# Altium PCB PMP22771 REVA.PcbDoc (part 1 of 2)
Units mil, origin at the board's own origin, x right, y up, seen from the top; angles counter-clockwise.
Board outline 3622.05 x 2204.72 mil, 4 copper layers (Top Layer, Signal Layer 1, Signal Layer 2, Bottom Layer), stack 35.634 mil thick; 91 components, 43 nets, 205 pads, 79 vias.
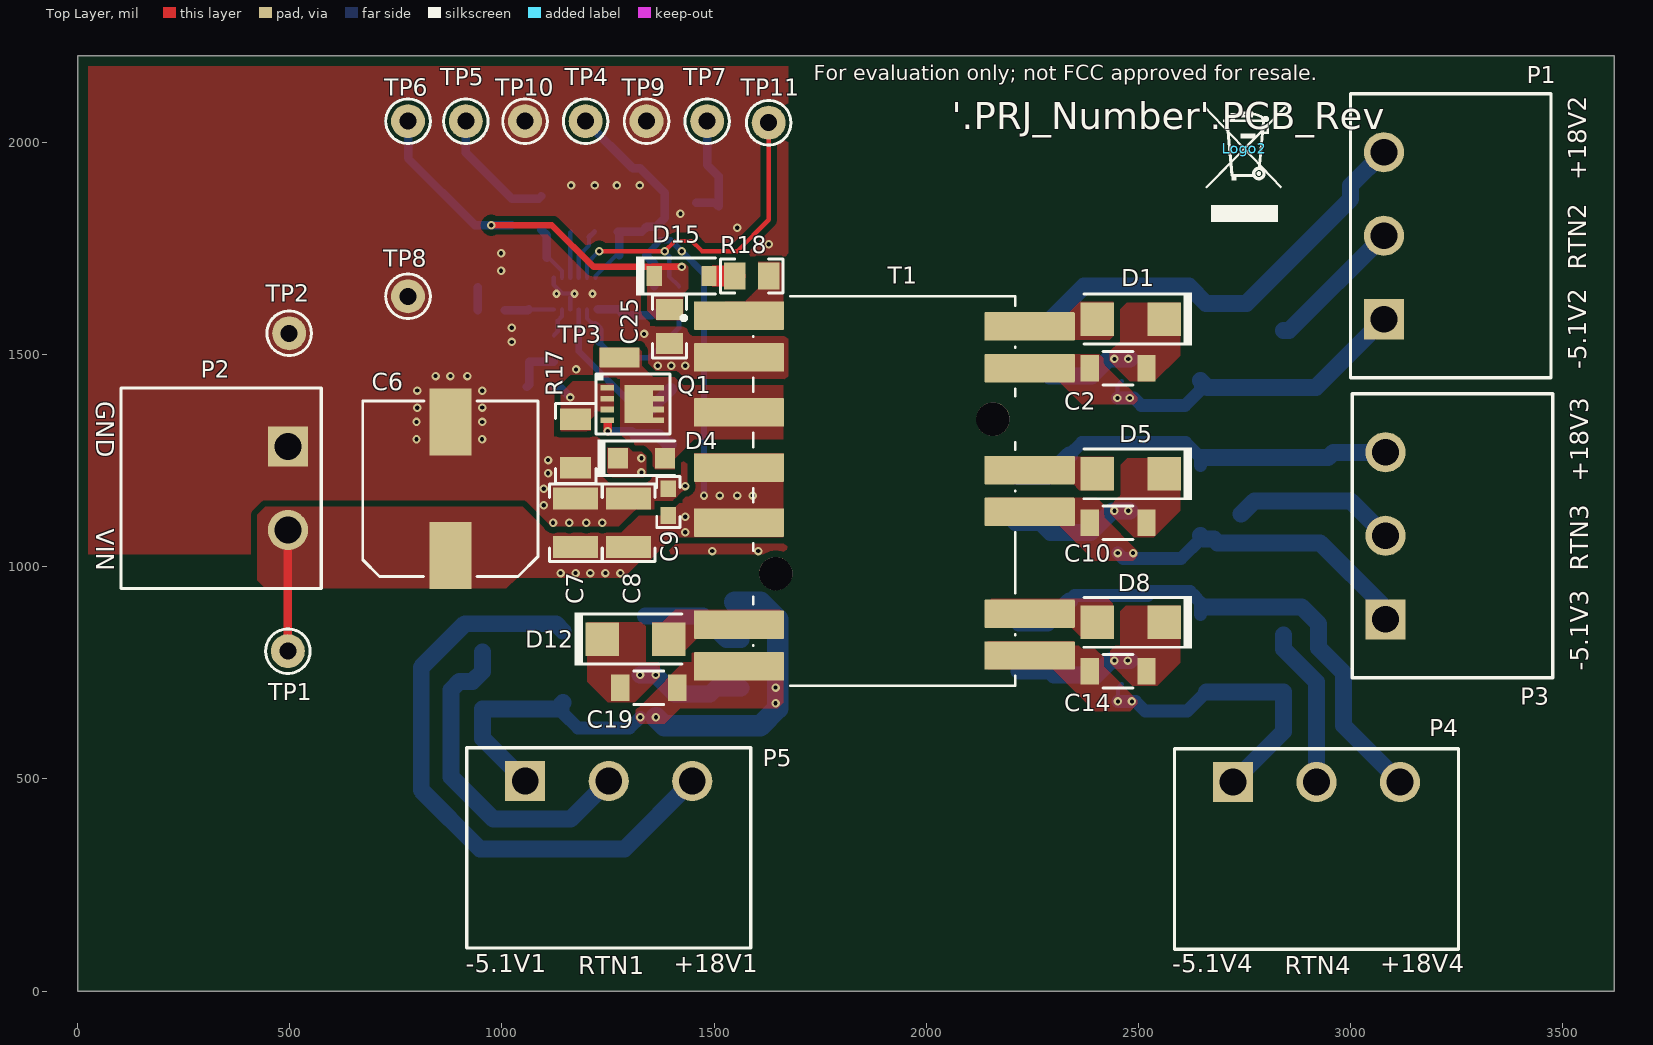
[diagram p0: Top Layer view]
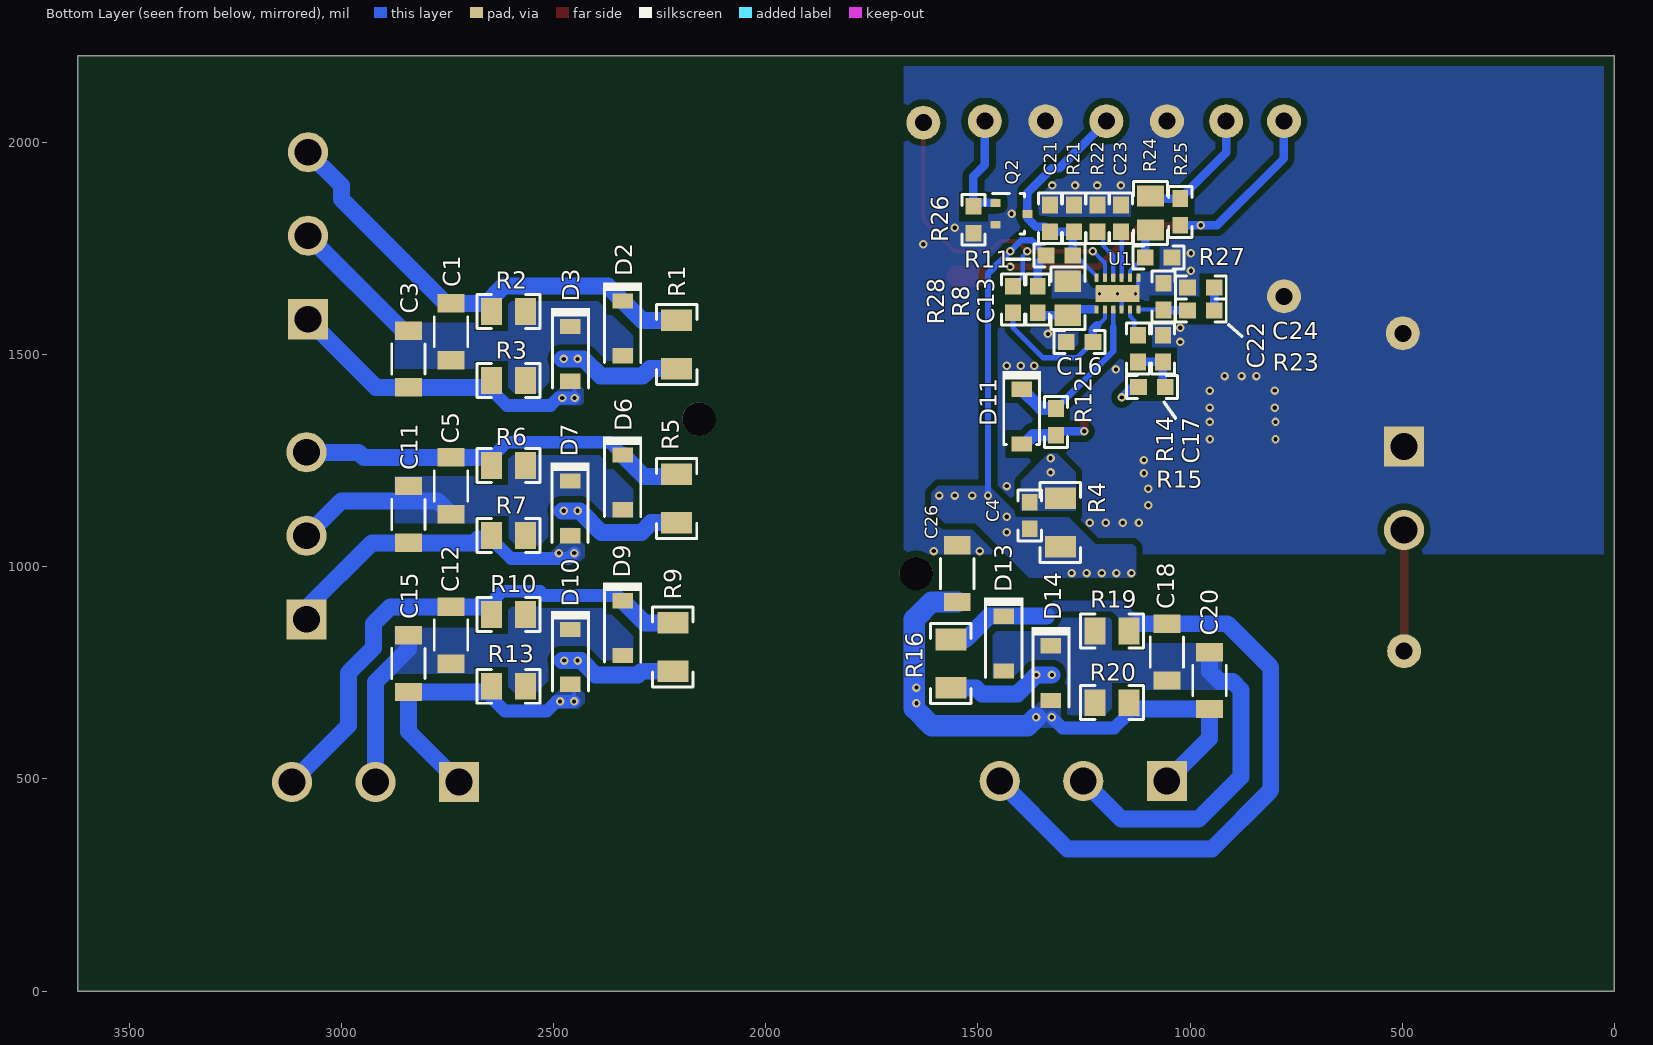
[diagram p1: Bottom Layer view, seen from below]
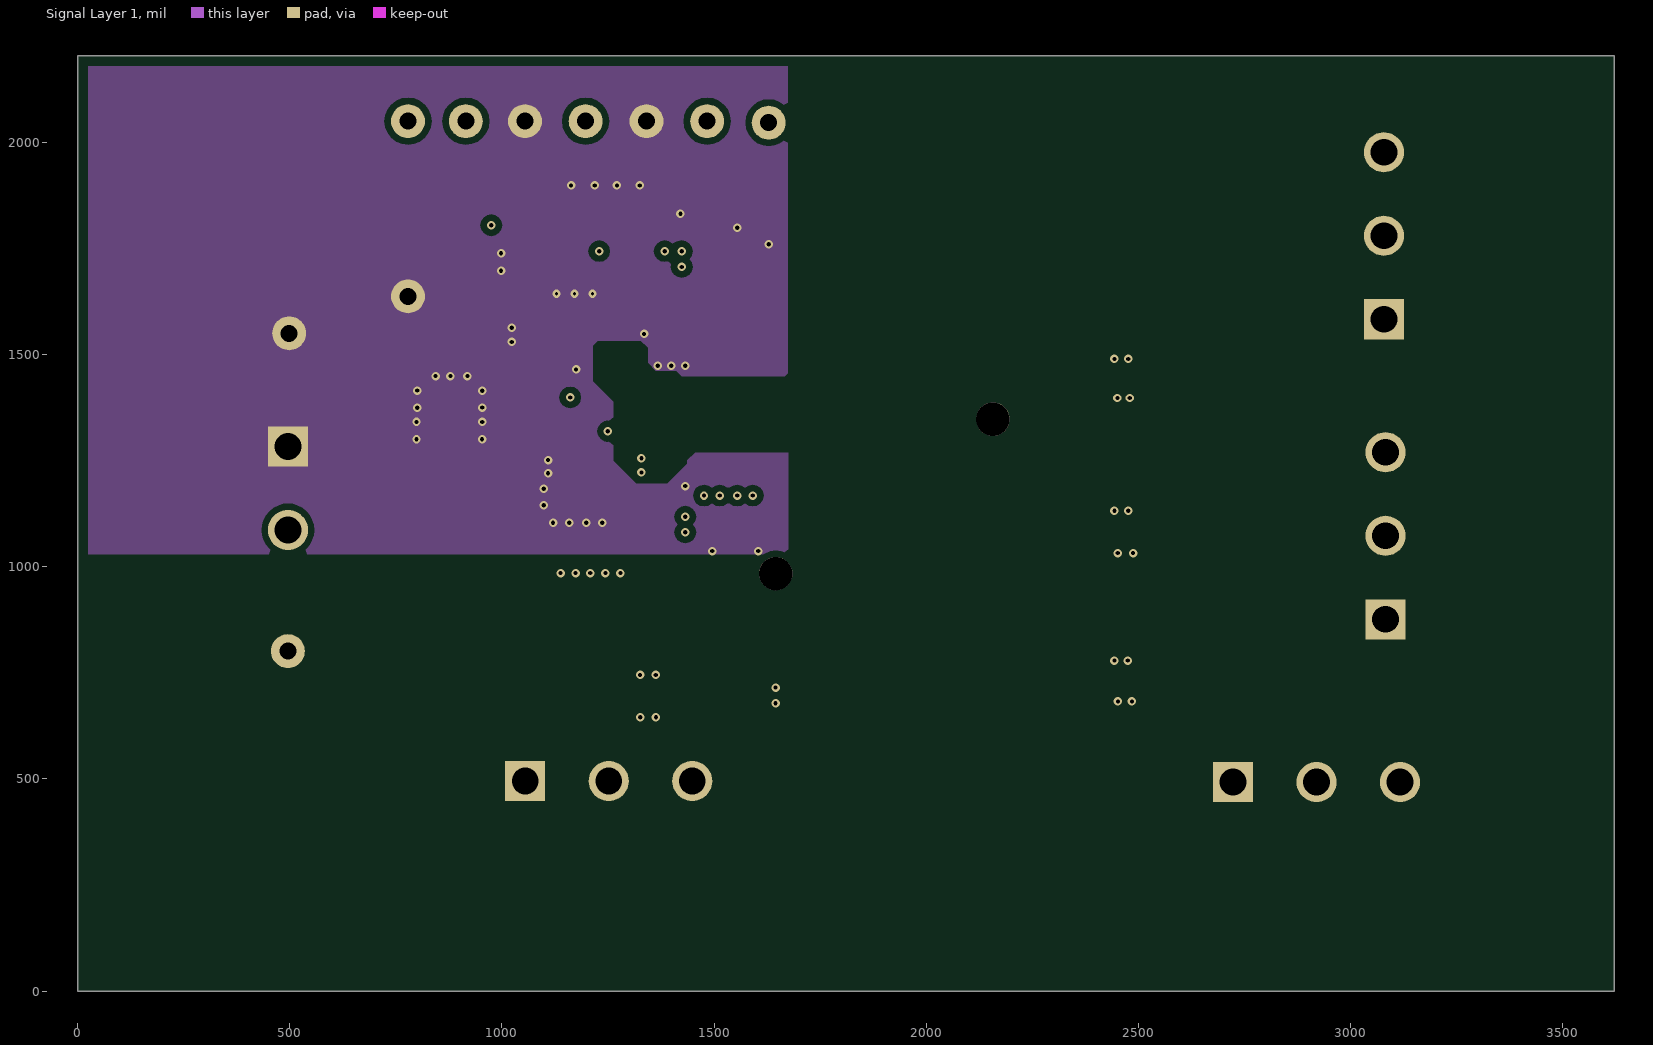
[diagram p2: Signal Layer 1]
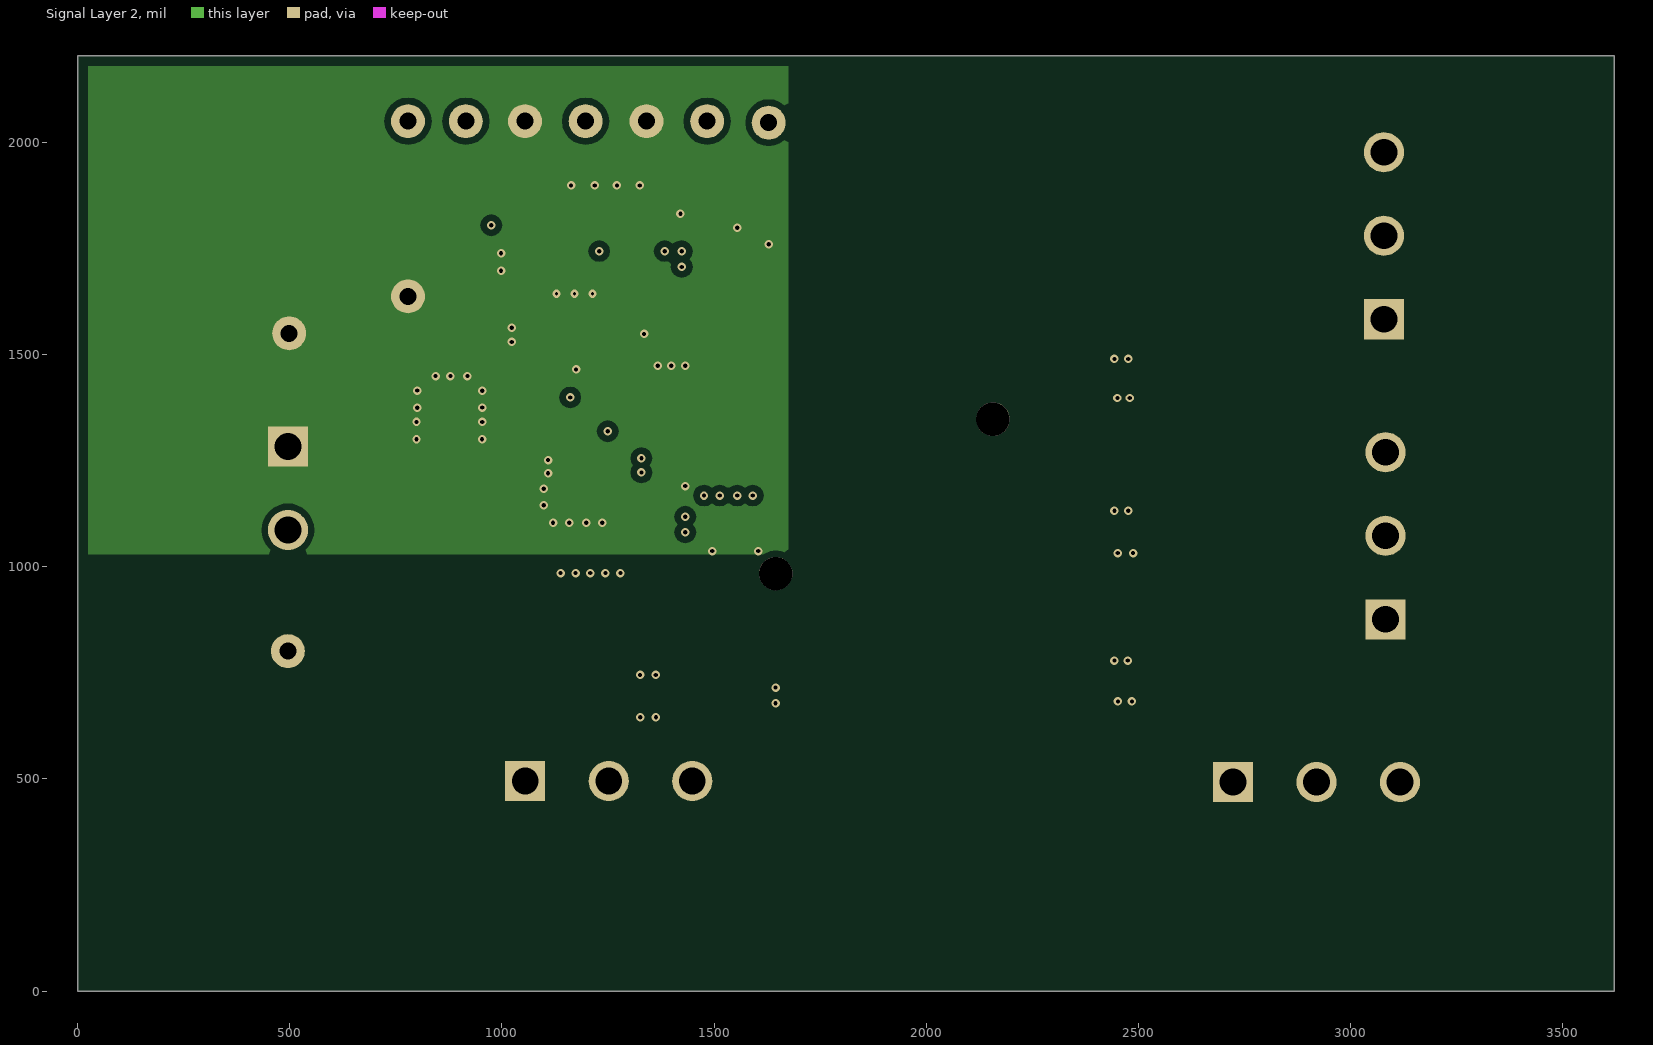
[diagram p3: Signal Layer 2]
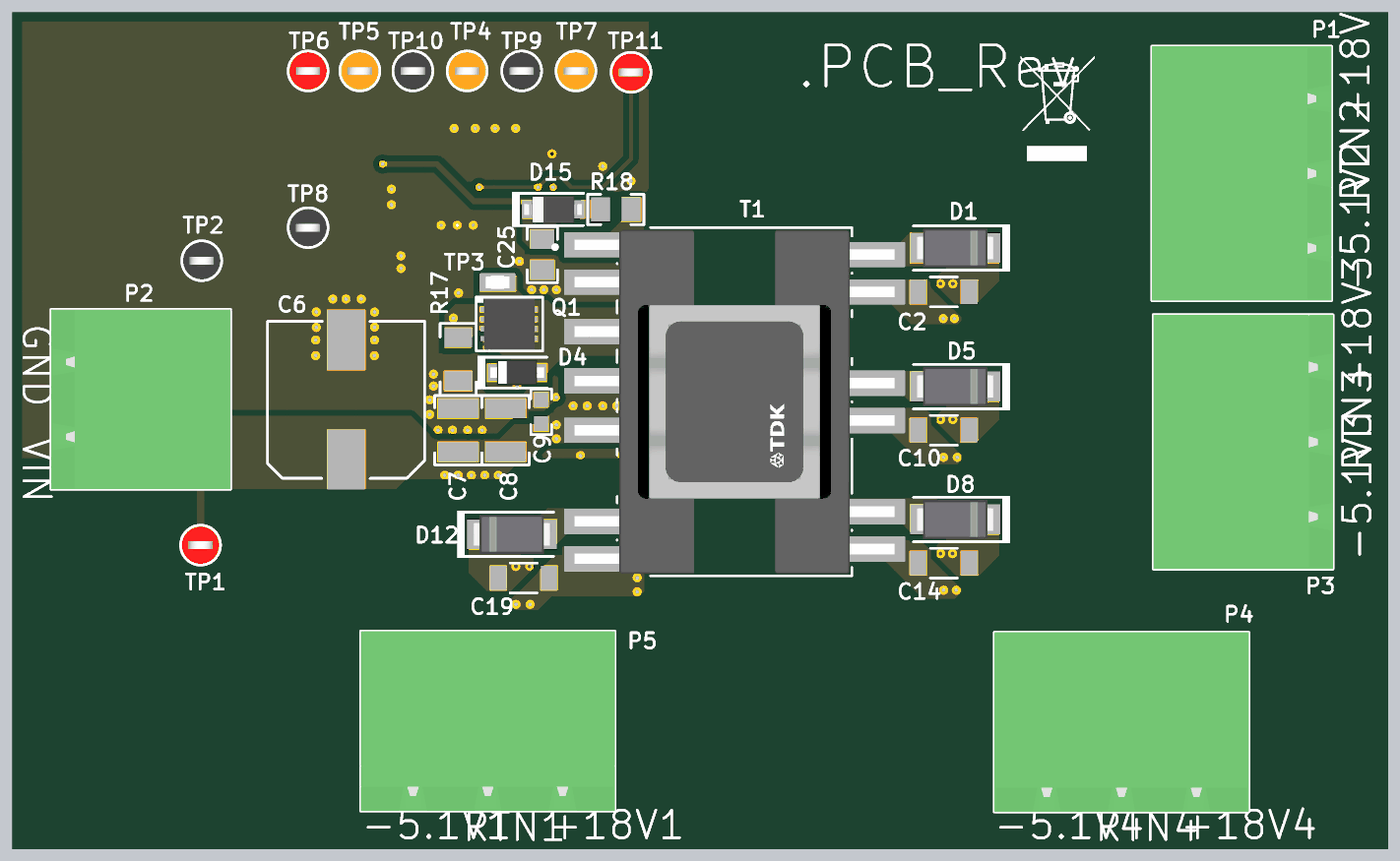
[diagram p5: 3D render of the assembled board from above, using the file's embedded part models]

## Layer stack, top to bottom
Top Solder: solder mask 0.4, Solder Resist, Dk 3.5
Top Layer: signal copper 1.4
Dielectric1: core 10, FR-4, Dk 4.2
Signal Layer 1: signal copper 1.417
Dielectric 2: core 10, Dk 4.2
Signal Layer 2: signal copper 1.417
Dielectric 3: core 10, FR-4, Dk 4.2
Bottom Layer: signal copper 1.4
Bottom Solder: solder mask 0.4, Solder Resist, Dk 3.5

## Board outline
0,0 3622.05,0 3622.05,2204.72 0,2204.72

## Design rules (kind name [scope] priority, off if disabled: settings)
AcuteAngle [All] p1: minimum=4.50000000000000E+0001 checktracksonly=FALSE
AssemblyTestPointUsage [All] p1: valid=2
BoardOutlineClearance BoardOutlineClearance_MountingHoles [OnCopper and InComponentClass('Mounting Holes')] p1: gap=39.37 ignorepadtopadclearanceinfootprint=FALSE
BoardOutlineClearance BoardOutlineClearance_Poly [OnCopper and IsPoly] p2: gap=25 ignorepadtopadclearanceinfootprint=FALSE
BoardOutlineClearance [OnCopper and Not InComponentClass('Logo') and not InComponentClass('FiducialMark') and not InRegion(1000,500,4000,800) and not InPoly] p3: gap=50 ignorepadtopadclearanceinfootprint=FALSE
Clearance Clearance_Keepouts [((IsTrack Or IsArc) And Not InPoly) And IsFree and IsKeepOut vs ((IsTrack Or IsArc) And Not InPoly) And IsFree and IsKeepOut] p1: gap=0 ignorepadtopadclearanceinfootprint=FALSE
Clearance Clearance_Poly [InPolygon] p2: gap=15 ignorepadtopadclearanceinfootprint=TRUE
Clearance Clearance_FiducialMark [IsKeepOut and InComponentClass('FiducialMark') vs IsPad and InComponentClass('FiducialMark')] p3: gap=0 ignorepadtopadclearanceinfootprint=FALSE
Clearance [All] p4: gap=7.87 ignorepadtopadclearanceinfootprint=TRUE
ComponentClearance ComponentClearance_MountingHoles_FiducialMarks [InComponentClass('Mounting Holes') vs InComponentClass('FiducialMark')] p1: gap=50 collisioncheckmode=3 verticalgap=10 showdistances=FALSE
ComponentClearance ComponentClearance_Shunt [InComponentClass('Header') vs InComponentClass('Shunt')] p2: gap=0 collisioncheckmode=3 verticalgap=0 showdistances=FALSE
ComponentClearance ComponentClearance_Logo [InComponentClass('Logo')] p3: gap=50 collisioncheckmode=3 verticalgap=10 showdistances=FALSE
ComponentClearance ComponentClearance_ScrewToNut [(HasFootprint('NY PMS 440 0025 PH')) vs (HasFootprint('Keystone_1902C'))] p4: gap=5 collisioncheckmode=3 verticalgap=10 showdistances=FALSE
ComponentClearance ComponentClearance_MountingHoles [InComponentClass('Mounting Holes')] p5: gap=250 collisioncheckmode=3 verticalgap=100000 showdistances=FALSE
ComponentClearance ComponentClearance_SmallPassives [HasFootprint('0201*') or HasFootprint('0402*') or HasFootprint('0508') or HasFootprint('0603*') or HasFootprint('0612') or HasFootprint('0805*') or HasFootprint('0815*') or HasFootprint('0830*') or HasFootprint('1206*') or HasFootprint('1210*') or HasFootprint('1808*') or HasFootprint('1812*') or HasFootprint('1825*') or HasFootprint('2010*') or HasFootprint('2220*') or HasFootprint('2225*') or HasFootprint('2512*') or HasFootprint('2728*') or HasFootprint('3518*') vs HasFootprint('0201*') or HasFootprint('0402*') or HasFootprint('0508') or HasFootprint('0603*') or HasFootprint('0612') or HasFootprint('0805*') or HasFootprint('0815*') or HasFootprint('0830*') or HasFootprint('1206*') or HasFootprint('1210*') or HasFootprint('1808*') or HasFootprint('1812*') or HasFootprint('1825*') or HasFootprint('2010*') or HasFootprint('2220*') or HasFootprint('2225*') or HasFootprint('2512*') or HasFootprint('2728*') or HasFootprint('3518*')] p6: gap=14.96 collisioncheckmode=3 verticalgap=10 showdistances=FALSE
ComponentClearance ComponentClearance_THtoSMT [IsThruComponent vs IsSMTComponent] p7: gap=25 collisioncheckmode=3 verticalgap=25 showdistances=FALSE
ComponentClearance ComponentClearance_THtoTH [IsThruComponent vs IsThruComponent] p8: gap=30 collisioncheckmode=3 verticalgap=30 showdistances=FALSE
ComponentClearance [All] p9: gap=25 collisioncheckmode=3 verticalgap=10 showdistances=FALSE
DiffPairsRouting [All] p1: maxlimit=100 minlimit=10 mostfreqgap=10 toplayer_minwidth=15 toplayer_maxwidth=15 toplayer_prefwidth=15 midlayer1_minwidth=15 midlayer1_maxwidth=15 midlayer1_prefwidth=15 midlayer2_minwidth=15 midlayer2_maxwidth=15 midlayer2_prefwidth=15 bottomlayer_minwidth=15 bottomlayer_maxwidth=15 bottomlayer_prefwidth=15 maxuncoupledlength=1000
FabricationTestPointUsage TestPointUsage [All] p1: valid=2 allowmultiple=FALSE
FabricationTestpoint Testpoint [All] p1: side=3 testpointundercomponent=TRUE minsize=40 maxsize=100 preferedsize=60 minholesize=0 maxholesize=40 preferedholesize=32 testpointgrid=1 allowsidetop=TRUE allowsidebottom=TRUE usegrid=TRUE gridtolerance=0.01
FanoutControl Fanout_LCC [IsLCC] p1: bgadir=Out bgaviamode=Centered fanoutstyle=Auto fanoutdirection=Alternating viagrid=1 // Fanout_LCC (Default Rule)
FanoutControl Fanout_BGA [IsBGA] p2: bgadir=Out bgaviamode=Centered fanoutstyle=Auto fanoutdirection=Alternating viagrid=1 // Fanout_BGA (Default Rule)
FanoutControl Fanout_Default [All] p4: bgadir=Out bgaviamode=Centered fanoutstyle=Auto fanoutdirection=Alternating viagrid=1 // Fanout_Default (Default Rule)
FanoutControl Fanout_Small [(CompPinCount < 5)] p5: bgadir=Out bgaviamode=Centered fanoutstyle=Auto fanoutdirection=OutThenIn viagrid=1 // Fanout_Small (Default Rule)
HoleSize [All] p1: absolutevalues=TRUE maxlimit=251 minlimit=7.87 maxpercent=80.000 minpercent=20.000
MinimumAnnularRing MinimumAnnularRing_ThermalPadVias [IsVia and InAnyComponent] p1: minimumring=4.9
MinimumAnnularRing [All] p2: minimumring=4.9
MinimumSolderMaskSliver MinimumSolderMaskSliver_Logo [InComponentClass('Logo') vs InComponentClass('Logo')] p1: minsoldermaskwidth=0.7
MinimumSolderMaskSliver [All] p2: minsoldermaskwidth=3.94
PlaneClearance [All] p1: clearance=12
PlaneConnect [All] p1: planeconnectstyle=Direct reliefexpansion=10 reliefentries=4 reliefconductorwidth=10 reliefairgap=10
PolygonConnect [All] p1: connectstyle=Direct reliefconductorwidth=10 reliefentries=4 polygonreliefangle="90 Angle" airgapwidth=10
RoutingVias ThermalPadVias [IsVia and InAnyComponent] p1: holewidth=7.87 width=19.68 viastyle="Through Hole" minholewidth=7.87 minwidth=19 maxholewidth=12.99 maxwidth=100
RoutingVias [All] p2: holewidth=16 width=34 viastyle="Through Hole" minholewidth=7.87 minwidth=19 maxholewidth=40 maxwidth=100
SilkToBoardRegionClearance [Not ((IsComment or IsDesignator) And (Hide <> 'False')) and not InRegion(1000,500,4000,800)] p1:
SilkToSilkClearance SilkToSilkClearance_Pb-FreeLogo [(HasFootprint('Pb-Free_Overlay_Medium') OR HasFootprint('Pb-Free_Overlay_Small')) vs (HasFootprint('Pb-Free_Overlay_Medium') OR HasFootprint('Pb-Free_Overlay_Small'))] p1: silktosilkclearance=0
SilkToSilkClearance [All] p2: silktosilkclearance=0
SilkToSolderMaskClearance SilkToComponentPadClearance [(IsPad or IsFill or IsRegion) and InAnycomponent] p1: minsilkscreentomaskgap=0 clearancetoexposedcopper=TRUE
SilkToSolderMaskClearance "Silk to Solder Mask Opening" [All] p2: minsilkscreentomaskgap=0 clearancetoexposedcopper=FALSE
SolderMaskExpansion [All] p1: expansion=1.97
UnRoutedNet [All] p1: checkbadconnections=TRUE
Width [All] p1: maxlimit=100 minlimit=6 preferedwidth=10 checkconnectedcopper=TRUE
13 further rules are at their usual default settings.

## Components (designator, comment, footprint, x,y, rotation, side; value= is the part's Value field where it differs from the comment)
C1 "CGA5L1X7R1E106K160AE" 1206_190 2741.84,1553.72 r270 bottom value=10uF
C2 "CGA5L3X7R1H475K160AE" 1206_190 2452.24,1467.93 r180 top value=4.7uF
C3 "CGA5L1X7R1E106K160AE" 1206_190 2842.24,1489.58 r270 bottom value=10uF
C4 "GCM188R71H103KA37D" 0603 1377.95,1120.77 r90 bottom value=0.01uF
C5 "CGA5L1X7R1E106K160AE" 1206_190 2741.84,1190.65 r270 bottom value=10uF
C6 "EEHZC1H101P" SM_RADIAL_10BMM 878.82,1183.76 r90 top value=100uF
C7 "GRM32ER71H106KA12L" 1210_270 1173.82,1103.76 r90 top value=10uF
C8 "GRM32ER71H106KA12L" 1210_270 1298.82,1103.76 r90 top value=10uF
C9 "GCM188R71H104KA57D" 0603 1392.27,1152.26 r90 top value=0.1uF
C10 "CGA5L3X7R1H475K160AE" 1206_190 2452.24,1103.68 r180 top value=4.7uF
C11 "CGA5L1X7R1E106K160AE" 1206_190 2842.24,1123.25 r270 bottom value=10uF
C12 "CGA5L1X7R1E106K160AE" 1206_190 2741.84,838.72 r270 bottom value=10uF
C13 "Capacitor" 0805_HV 1288.22,1632.62 r90 bottom value=1uF
C14 "CGA5L3X7R1H475K160AE" 1206_190 2452.24,753.72 r180 top value=4.7uF
C15 "CGA5L1X7R1E106K160AE" 1206_190 2842.24,771.79 r270 bottom value=10uF
C16 "GCM188R71E105KA64D" 0603 1260.6,1529.88 r0 bottom value=1uF
C17 "GCM1885C1H102JA16D" 0603 1064.12,1514.15 r90 bottom value=1000pF
C18 "CGA5L1X7R1E106K160AE" 1206_190 1054.62,798.72 r270 bottom value=10uF
C19 "CGA5L3X7R1H475K160AE" 1206_190 1346.06,714.57 r0 top value=4.7uF
C20 "CGA5L1X7R1E106K160AE" 1206_190 954.29,731.79 r270 bottom value=10uF
C21 "GRM1885C1H100JA01D" 0603 1330.13,1821.22 r90 bottom value=10pF
C22 "GRM188R71H331KA01D" 0603 1062.35,1636.63 r90 bottom value=330pF
C23 "CGA3E2X7R1H104K080AA" 0603 1163.22,1821.22 r90 bottom value=0.1uF
C24 "CGA3E3X7S2A333K080AB" 0603 974.87,1658.29 r0 bottom value=0.033uF
C25 "Capacitor" 0805_HV 1395.31,1566.36 r270 top value=1uF
C26 "C1206C102KGRACAUTO" 1206_180 1548.82,983.68 r90 bottom value=1000pF
D1 "ES1D-13-F" SMA 2482.24,1583.72 r180 top value=200V
D2 "Zener" SOD-123 2337.24,1561.72 r270 bottom value=18V
D3 "Zener" SOD-123 2460.63,1501.48 r270 bottom value=5.1V
D4 "DIODE_SCHOTTKY" SOD-123F 1328.82,1255.67 r0 top value=100V
D5 "ES1D-13-F" SMA 2482.24,1218.72 r180 top value=200V
D6 "Zener" SOD-123 2337.24,1198.72 r270 bottom value=18V
D7 "Zener" SOD-123 2461.11,1137.39 r270 bottom value=5.1V
D8 "ES1D-13-F" SMA 2482.24,868.72 r180 top value=200V
D9 "Zener" SOD-123 2337.24,855.1 r270 bottom value=18V
D10 "Zener" SOD-123 2460.63,787.4 r270 bottom value=5.1V
D11 "MBR130LSFT1G" SOD-123FL 1397.24,1353.72 r270 bottom value=30V
D12 "ES1D-13-F" SMA 1314.96,829.57 r0 top value=200V
D13 "Zener" SOD-123 1439.24,818.9 r270 bottom value=18V
D14 "Zener" SOD-123 1328.22,749.47 r270 bottom value=5.1V
D15 "BAT41ZFILM" SOD-123 1423.82,1685.18 r0 top value=100V
Logo1 "FCC disclaimer" FCC_disclaimer 6971.49,-194.91 r90 top
Logo2 "WEEE logo" WEEE_Minimum 2750,1985 r0 top
P1 "691313710003" 691313710003 3236.18,1780 r90 top
P2 "691313710002" 691313710002 338.46,1184.94 r270 top
P3 "691313710003" 691313710003 3240,1072.92 r90 top
P4 "691313710003" 691313710003 2920,335 r0 top
P5 "691313710003" 691313710003 1251.85,337.52 r0 top
Q1 "MOSFET_N_D56789G4S123" PG-TSDSON-8 1308.7,1383.29 r0 top value=80V
Q2 "2N7002W-7-F" SOT-323 1420.82,1831.67 r180 bottom value=60V
R1 "CRCW12064R70JNEAHP" 1206 2210.09,1523.72 r90 bottom value=4.7
R2 "Resistor" 0805_HV 2606.65,1601.72 r0 bottom value=17.8k
R3 "Resistor" 0805_HV 2606.65,1438.72 r180 bottom value=5.11k
R4 "CRCW12061K50JNEA" 1206 1305.89,1103.97 r270 bottom value=1.5k
R5 "CRCW12064R70JNEAHP" 1206 2210.39,1160.81 r90 bottom value=4.7
R6 "Resistor" 0805_HV 2606.65,1238.72 r0 bottom value=17.8k
R7 "Resistor" 0805_HV 2606.24,1073.72 r180 bottom value=5.11k
R8 "Resistor" 0603 1359.25,1629.74 r90 bottom value=10.0
R9 "CRCW12064R70JNEAHP" 1206 2218.98,810.78 r90 bottom value=4.7
R10 "Resistor" 0805_HV 2606.65,887.6 r0 bottom value=17.8k
R11 "CRCW0603200KFKEA" 0603 1308.22,1733.72 r0 bottom value=200k
R12 "Resistor" 0603 1316.18,1341.24 r270 bottom value=10.0
R13 "Resistor" 0805_HV 2606.65,718.26 r180 bottom value=5.11k
R14 "Resistor" 0603 1122.57,1514.15 r270 bottom value=0
R15 "Resistor" 0603 1090.27,1423.72 r0 bottom value=100
R16 "CRCW12064R70JNEAHP" 1206 1563.7,771.65 r90 bottom value=4.7
R17 "ERJ-8CWFR024V" 1206 1173.82,1290.18 r90 top value=0.015
R18 "CRCW080510R0FKEA" 0805_HV 1588.82,1685.18 r0 top value=10.0
R19 "Resistor" 0805_HV 1184.16,848.72 r180 bottom value=17.8k
R20 "Resistor" 0805_HV 1184.29,679.57 r0 bottom value=5.11k
R21 "CRCW060360K4FKEA" 0603 1273.4,1821.22 r270 bottom value=60.4k
R22 "CRCW060354K9FKEA" 0603 1218.22,1821.22 r270 bottom value=54.9k
R23 "CRCW060315K0FKEA" 0603 974.87,1604.11 r0 bottom value=15.0k
R24 "Resistor" 0805_HV 1093.22,1833.72 r90 bottom value=10.0k
R25 "Resistor" 0603 1023.22,1836.24 r270 bottom value=49.9
R26 "CRCW060310K0FKEA" 0603 1510.85,1817.71 r90 bottom value=10.0k
R27 "Resistor" 0603 1074.4,1728.72 r0 bottom value=432
R28 "CRCW060310K0FKEA" 0603 1417.32,1629.74 r270 bottom value=10.0k
T1 "VGT15SEFD-250S4A7" FP-VGT15SEFD-250S4A7_SMT_TRANSFORMER_23MM0_15MM4-MFG 1901.34,1178.56 r90 top
TP1 "5000" Keystone5000 495.71,801.08 r90 top
TP2 "5001" Keystone5001 498.82,1550.18 r90 top
TP3 "RCU-0C" TE_RCU 1277.56,1493.4 r0 top
TP4 "ENABLE" Keystone5003 1197.37,2050 r90 top
TP5 "5003" Keystone5003 915,2050 r90 top
TP6 "5000" Keystone5000 778.82,2050 r90 top
TP7 "/ENABLE" Keystone5003 1483.82,2050 r90 top
TP8 "5001" Keystone5001 778.82,1637.22 r90 top
TP9 "5001" Keystone5001 1340.96,2050 r90 top
TP10 "5001" Keystone5001 1054.62,2050 r90 top
TP11 "5000" Keystone5000 1628.82,2046.46 r90 top
U1 "LM51551QDSSTQ1" DSS0012C 1171.25,1643.72 r90 bottom

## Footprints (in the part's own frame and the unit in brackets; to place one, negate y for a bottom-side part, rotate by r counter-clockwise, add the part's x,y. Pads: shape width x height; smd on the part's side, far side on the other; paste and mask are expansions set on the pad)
0603 [mm] "0603 from SM-752 data"
  rect 1x0.95 smd: 1(-0.8,0) 2(0.8,0)
  silkscreen extent -1.52,-0.69 1.52,0.69, body extent -0.87,-0.47 0.87,0.47, height 1
0805_HV [mil] "0805 with 30mil clearance between pads"
  rect 50x63 smd: 1(-40,0) 2(40,0)
  silkscreen extent -74,-40 74,40, body extent -43,-29 43,29, height 57
1206 [mm] "1206 from SM-752 data"
  rect 1.3x1.85 smd: 1(-1.45,0) 2(1.45,0)
  silkscreen extent -2.4,-1.21 2.4,1.21, body extent -1.7,-0.9 1.7,0.9, height 1.35
1206_180 [mm] "1206_180"
  rect 1.1x1.6 smd: 1(-1.7,0) 2(1.7,0)
  silkscreen extent -0.9,-1 0.9,1, body extent -1.75,-0.95 1.75,0.95, height 1.8
1206_190 [mm] "1206_190"
  rect 1.1x1.6 smd: 1(-1.7,0) 2(1.7,0)
  silkscreen extent -0.9,-1 0.9,1, body extent -1.75,-0.95 1.75,0.95, height 1.9
1210_270 [mm] "1210"
  rect 1.3x2.7 smd: 1(-1.45,0) 2(1.45,0)
  silkscreen extent -2.32,-1.57 2.32,1.57, body extent -1.7,-1.35 1.7,1.35, height 2.7
691313710002 [mm] "5.00mm - Closed Horizhontal PCB Header - -02p"
  rect 2.4x2.4 hole 1.6: 1(-2.5,4)
  round 2.4 hole 1.6: 2(2.5,4)
  silkscreen extent -6,-6 6,6, body extent -6,-6 6,6, height 8.55
691313710003 [mm] "5.00mm - Closed Horizhontal PCB Header - -03p"
  rect 2.4x2.4 hole 1.6: 1(-5,4)
  round 2.4 hole 1.6: 2(0,4) 3(5,4)
  silkscreen extent -8.5,-6 8.5,6, body extent -8.5,-6 8.5,6, height 8.55
DSS0012C [mm] "WSON-12"
  rrect40% 0.5x0.25 smd: 1(-0.95,1.25) 2(-0.95,0.75) 3(-0.95,0.25) 4(-0.95,-0.25) 5(-0.95,-0.75) 6(-0.95,-1.25) 7(0.95,-1.25) 8(0.95,-0.75) 9(0.95,-0.25) 10(0.95,0.25) 11(0.95,0.75) 12(0.95,1.25)
  rrect11% 0.95x1.17 on Bottom Paste: 13(0,-0.685) 13(0,0.685)
  rrect11% 1x2.65 smd paste-0.5: 13(0,0)
  body extent -1,-1.5 1,1.5, height 0.81
FCC_disclaimer [mil]
FP-VGT15SEFD-250S4A7_SMT_TRANSFORMER_23MM0_15MM4-MFG [mm]
  rrect6% 1.7x5.4 smd paste+0 mask+0: 1(10.5,8.7) 2(8,8.7) 3(4.7,8.7) 4(1.4,8.7) 5(-1.9,8.7) 6(-8,8.7) 7(-10.5,8.7) 8(-9.85,-8.7) 9(-7.35,-8.7) 10(-1.25,-8.7) 11(1.25,-8.7) 12(7.35,-8.7) 13(9.85,-8.7)
  round 2 hole 2 unplated paste-1000 mask+0: ""(-4.95,6.5) ""(4.3,-6.5)
  silkscreen extent -11.65,-7.85 11.65,12.12, body extent -11.75,-11.5 11.75,11.5, height 0.25
Keystone5000 [mil] "For Keystone 500x miniature loop terminals"
  round 80 hole 40: 1(0,0)
  silkscreen extent -52,-52 52,52, body extent -49,-49 49,49, height 182
Keystone5001 [mil] "For Keystone 500x miniature loop terminals"
  round 80 hole 40: 1(0,0)
  silkscreen extent -52,-52 52,52, body extent -49,-49 49,49, height 182
Keystone5003 [mil] "For Keystone 500x miniature loop terminals"
  round 80 hole 40: 1(0,0)
  silkscreen extent -52,-52 52,52, body extent -49,-49 49,49, height 182
PG-TSDSON-8 [mm] "Infineon recommended land pattern"
  rect 0.8x0.34 smd: 1(-1.538,0.975) 2(-1.538,0.325) 3(-1.538,-0.325) 4(-1.538,-0.975)
  rect 0.65x0.34 smd: 5(1.538,-0.975) 6(1.538,-0.325) 7(1.538,0.325) 8(1.538,0.975)
  rect 1.71x2.29 smd: 9(0.358,0)
  silkscreen extent -2.22,-1.8 2.22,1.8, body extent -1.7,-1.7 1.7,1.7, height 1.1
SM_RADIAL_10BMM [mm] "Nichicon 10x10"
  rect 4x2.5 smd: 1(-4,0) 2(4,0)
  silkscreen extent -5.25,-5.25 5.25,5.25, body extent -5.25,-5.25 5.25,5.25, height 10.5
SMA [mm] "Molded Diode, 2-Leads, Body 4.3x2.6mm, IPC Medium Density, based on OnSemi component dimensions and land pattern"
  rect 2x2 smd: 1(-2,0) 2(2,0)
  silkscreen extent -3.66,-1.57 2.79,1.57, body extent -2.6,-1.3 2.6,1.3, height 2.42
SOD-123 [mm] "On Semi recommended land pattern"
  rect 0.915x1.22 smd: 1(-1.637,0) 2(1.637,0)
  silkscreen extent -2.74,-1.17 2.03,1.17, body extent -1.93,-0.9 1.93,0.9, height 1.35
SOD-123F [mm] "NXP recommended land pattern"
  rect 1.2x1.2 smd paste-0.05: 1(-1.4,0) 2(1.4,0)
  silkscreen extent -2.64,-1.12 2.01,1.12, body extent -1.8,-0.85 1.8,0.85, height 1.2
SOD-123FL [mm] "Copied from SOD-123"
  rect 0.915x1.22 smd: 1(-1.637,0) 2(1.637,0)
  silkscreen extent -2.74,-1.16 1.68,1.16, body extent -1.9,-0.9 1.9,0.9, height 1
SOT-323 [mm] "Diodes Inc recommended land pattern.  2016-02-24"
  rrect21% 0.6x0.47 smd: 1(-0.95,0.65) 2(-0.95,-0.65) 3(0.95,0)
  silkscreen extent -1.14,-1.22 0.77,1.22, body extent -1.13,-1.13 1.12,1.12, height 1.13
TE_RCU [mm] "SMD, 1-Leads, Body 1.6x0.8mm"
  rrect8% 2.4x1.2 smd: 1(0,0)
  body extent -0.8,-0.45 0.8,0.45, height 1.15
WEEE_Minimum [mil] "WEEElie bin"
  silkscreen extent -95,-172 99,104

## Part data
C1 C3 C5 C11 C12 C15 C18 C20: library part CMP-0085253-1, "CAP, CERM, 10 µF, 25 V,+/- 10%, X7R, AEC-Q200 Grade 1, 1206", Cap_Case=1206, Manufacturer=TDK, TempCo=X7R, Tolerance_%=10%, Value2=25V, ValueDisplayed=10µF
C2 C10 C14 C19: library part CMP-0085349-1, "CAP, CERM, 4.7 µF, 50 V,+/- 10%, X7R, AEC-Q200 Grade 1, 1206", Cap_Case=1206, Manufacturer=TDK, TempCo=X7R, Tolerance_%=10%, Value2=50V, ValueDisplayed=4.7µF
C4: library part CMP-0007143-1, "CAP, CERM, 0.01 uF, 50 V, +/- 10%, X7R, AEC-Q200 Grade 1, 0603", Cap_Case=0603, Manufacturer=MuRata, Supplier Part Number 1=490-4778-1-ND, TempCo=X7R, Tolerance_%=10%, Value1=Unknown, Value2=50V, ValueDisplayed=0.01uF
C6: library part CMP-0012596-3, "CAP, Polymer Hybrid, 100 uF, 50 V, +/- 20%, 28 mohm, 10x10 SMD", Manufacturer=Panasonic, Supplier Part Number 1=P15462CT-ND, Tolerance_%=20%, Value1="0.028 ohm", Value2=50V, ValueDisplayed=100uF
C7 C8: library part CMP-0009226-3, "CAP, CERM, 10 uF, 50 V, +/- 10%, X7R, 1210", Cap_Case=1210, Manufacturer=MuRata, Supplier Part Number 1=490-6544-1-ND, TempCo=X7R, Tolerance_%=10%, Value1=Unknown, Value2=50V, ValueDisplayed=10uF
C9: library part CMP-0007144-4, "CAP, CERM, 0.1 uF, 50 V, +/- 10%, X7R, 0603", Cap_Case=0603, Manufacturer=MuRata, Supplier Part Number 1=490-4779-1-ND, TempCo=X7R, Tolerance_%=10%, Value1="0.02 ohm", Value2=50V, ValueDisplayed=0.1uF
C13 C25: library part CMP-0008350-2, "CAP, CERM, 1 uF, 50 V, +/- 10%, X7R, 0805", Cap_Case=0805, Manufacturer=MuRata, PartNumber=GRM21BR71H105KA12L, Supplier Part Number 1=490-4736-1-ND, TempCo=X7R, Tolerance_%=10%, Value1=Unknown, Value2=50V, ValueDisplayed=1uF
C16: library part CMP-0007139-4, "CAP, CERM, 1 uF, 25 V, +/- 10%, X7R, AEC-Q200 Grade 1, 0603", Cap_Case=0603, Manufacturer=MuRata, Supplier Part Number 1=490-10673-1-ND, TempCo=X7R, Tolerance_%=10%, Value1=Unknown, Value2=25V, ValueDisplayed=1uF
C17: library part CMP-0086079-1, "CAP, CERM, 1000 pF, 50 V,+/- 5%, C0G/NP0, AEC-Q200 Grade 1, 0603", Cap_Case=0603, Manufacturer=MuRata, TempCo=C0G/NP0, Tolerance_%=5%, Value2=50V, ValueDisplayed=1000pF
C21: library part CMP-0007170-4, "CAP, CERM, 10 pF, 50 V, +/- 5%, C0G/NP0, 0603", Cap_Case=0603, Manufacturer=MuRata, Supplier Part Number 1=490-1403-1-ND, TempCo=C0G/NP0, Tolerance_%=5%, Value1=Unknown, Value2=50V, ValueDisplayed=10pF
C22: library part CMP-0007449-4, "CAP, CERM, 330 pF, 50 V, +/- 10%, X7R, 0603", Cap_Case=0603, Manufacturer=MuRata, Supplier Part Number 1=490-1486-1-ND, TempCo=X7R, Tolerance_%=10%, Value1=Unknown, Value2=50V, ValueDisplayed=330pF
C23: library part CMP-0007078-4, "CAP, CERM, 0.1 uF, 50 V, +/- 10%, X7R, AEC-Q200 Grade 1, 0603", Cap_Case=0603, Manufacturer=TDK, Supplier Part Number 1=445-5666-1-ND, TempCo=X7R, Tolerance_%=10%, Value1="0.0296 ohm", Value2=50V, ValueDisplayed=0.1uF
C24: library part CMP-0007100-4, "CAP, CERM, 0.033 uF, 100 V, +/- 10%, X7S, AEC-Q200 Grade 1, 0603", Cap_Case=0603, Manufacturer=TDK, Supplier Part Number 1=445-6935-1-ND, TempCo=X7S, Tolerance_%=10%, Value1="0.139637 ohm", Value2=100V, ValueDisplayed=0.033uF
C26: library part CMP-0008579-2, "CAP, CERM, 1000 pF, 2000 V, +/- 10%, X7R, AEC-Q200 Grade 1, 1206", Cap_Case=1206, Manufacturer=Kemet, Supplier Part Number 1=399-12976-1-ND, TempCo=X7R, Tolerance_%=10%, Value1=Unknown, Value2=2000V, ValueDisplayed=1000pF
D1 D5 D8 D12: library part CMP-0029024-2, "Diode, Ultrafast, 200 V, 1 A, SMA", Manufacturer="Diodes Inc.", Value1=1A, Value2=0.92V
D2 D6 D9 D13: library part CMP-0005755-4, "Diode, Zener, 18 V, 500 mW, SOD-123", Manufacturer="Diodes Inc.", PartNumber=MMSZ5248B-7-F, Power_W=500mW, Value1=0.5W
D3 D7 D10 D14: library part CMP-0005802-3, "Diode, Zener, 5.1 V, 500 mW, SOD-123", Manufacturer="Diodes Inc.", PartNumber=MMSZ5231B-7-F, Power_W=500mW, Value1=0.5W
D4: library part CMP-0028632-2, "Diode, Schottky, 100 V, 0.25 A, SOD-123F", Manufacturer=Nexperia, PartNumber=BAT46WH,115, Value1=0.25A, Value2=0.85V
D11: library part CMP-0028889-2, "Diode, Schottky, 30 V, 1 A, AEC-Q101, SOD-123FL", Manufacturer="ON Semiconductor", Value1=1A, Value2=0.38V
D15: library part CMP-0028445-2, "Diode, Schottky, 100 V, 0.2 A, SOD-123", Manufacturer=STMicroelectronics, Value1=0.2A, Value2=1V
Logo1: library part CMP-0074847-1, "FCC_disclaimer"
Logo2: library part CMP-0074769-1
P1 P3 P4 P5: library part CMP-1502-02049-1, "Serie 3137 - 5.00mm Close Horizontal PCB Header WR-TBL, 3 pin", Manufacturer="Wurth Elektronik", Operating Temperature=-40to105degC
P2: library part CMP-1502-02048-1, "Serie 3137 - 5.00mm Close Horizontal PCB Header WR-TBL, 2 pin", Manufacturer="Wurth Elektronik", Operating Temperature=-40to105degC
Q1: library part CMP-0000911-1, "MOSFET, N-CH, 80 V, 23 A, PG-TSDSON-8", Alternate Manufacturer=None, Manufacturer="Infineon Technologies", PartNumber="BSZ340N08NS3 G", Supplier Part Number 1=BSZ340N08NS3GINCT-ND, Value2="6.8 nC"
Q2: library part CMP-0000776-1, "MOSFET, N-CH, 60 V, 0.115 A, SOT-323", Alternate Manufacturer=None, Manufacturer="Diodes Inc.", Supplier Part Number 1=2N7002W-FDICT-ND, Value1=7
R1 R5 R9 R16: library part CMP-0018694-3, "RES, 4.7, 5%, 0.75 W, AEC-Q200 Grade 0, 1206", Manufacturer=Vishay-Dale, Power_W=750mW, Supplier Part Number 1=541-4.7UACT-ND, TempCo="200 ppm/C", Tolerance_%=5%, Value2=0.75W, Value_Code=4R70, ValueDisplayed=4.7
R2 R6 R10 R19: library part CMP-0020932-3, "RES, 17.8 k, 1%, 0.125 W, AEC-Q200 Grade 0, 0805", Manufacturer=Vishay-Dale, PartNumber=CRCW080517K8FKEA, Power_W=125mW, Supplier Part Number 1=541-17.8KCCT-ND, TempCo="100 ppm/C", Tolerance_%=1%, Value2=0.125W, Value_Code=17k8, ValueDisplayed=17.8k
R3 R7 R13 R20: library part CMP-0021344-3, "RES, 5.11 k, 1%, 0.125 W, AEC-Q200 Grade 0, 0805", Manufacturer=Vishay-Dale, PartNumber=CRCW08055K11FKEA, Power_W=125mW, Supplier Part Number 1=541-5.11KCCT-ND, TempCo="100 ppm/C", Tolerance_%=1%, Value2=0.125W, Value_Code=5k11, ValueDisplayed=5.11k
R4: library part CMP-0018607-3, "RES, 1.5 k, 5%, 0.25 W, AEC-Q200 Grade 0, 1206", Manufacturer=Vishay-Dale, Power_W=250mW, Supplier Part Number 1=541-1.5KECT-ND, TempCo="200 ppm/C", Tolerance_%=5%, Value2=0.25W, Value_Code=1k50, ValueDisplayed=1.5k
R8 R12: library part CMP-0022003-4, "RES, 10.0, 1%, 0.1 W, AEC-Q200 Grade 0, 0603", Manufacturer=Vishay-Dale, PartNumber=CRCW060310R0FKEA, Power_W=100mW, Supplier Part Number 1=541-10.0HCT-ND, TempCo="100 ppm/C", Tolerance_%=1%, Value2=0.1W, Value_Code=10R0, ValueDisplayed=10.0
R11: library part CMP-0022200-4, "RES, 200 k, 1%, 0.1 W, AEC-Q200 Grade 0, 0603", Manufacturer=Vishay-Dale, Power_W=100mW, Supplier Part Number 1=541-200KHCT-ND, TempCo="100 ppm/C", Tolerance_%=1%, Value2=0.1W, Value_Code=200k
R14: library part CMP-0025697-4, "RES, 0, 5%, 0.1 W, AEC-Q200 Grade 0, 0603", Manufacturer=Vishay-Dale, PartNumber=CRCW06030000Z0EA, Power_W=100mW, Supplier Part Number 1=541-0.0GCT-ND, TempCo="200 ppm/C", Tolerance_%=5%, Value2=0.1W, Value_Code=0000, ValueDisplayed=0
R15: library part CMP-0021991-4, "RES, 100, 1%, 0.1 W, AEC-Q200 Grade 0, 0603", Manufacturer=Vishay-Dale, PartNumber=CRCW0603100RFKEA, Power_W=100mW, Supplier Part Number 1=541-100HCT-ND, TempCo="100 ppm/C", Tolerance_%=1%, Value2=0.1W, Value_Code=100R, ValueDisplayed=100
R17: library part CMP-0750151-1, "RES, 0.024, 1%, 1 W, AEC-Q200 Grade 0, 1206", Manufacturer=Panasonic, Power_W=1W, Supplier Part Number 1=P0.024BVCT-ND, TempCo="200 ppm/C", Tolerance_%=1%, ValueDisplayed=0.024
R18: library part CMP-0020847-3, "RES, 10.0, 1%, 0.125 W, AEC-Q200 Grade 0, 0805", Manufacturer=Vishay-Dale, Power_W=125mW, Supplier Part Number 1=541-10.0CCT-ND, TempCo="100 ppm/C", Tolerance_%=1%, Value2=0.125W, Value_Code=10R0, ValueDisplayed=10.0
R21: library part CMP-0022532-4, "RES, 60.4 k, 1%, 0.1 W, AEC-Q200 Grade 0, 0603", Manufacturer=Vishay-Dale, Power_W=100mW, Supplier Part Number 1=541-60.4KHCT-ND, TempCo="100 ppm/C", Tolerance_%=1%, Value2=0.1W, Value_Code=60k4, ValueDisplayed=60.4k
R22: library part CMP-0022494-4, "RES, 54.9 k, 1%, 0.1 W, AEC-Q200 Grade 0, 0603", Manufacturer=Vishay-Dale, Power_W=100mW, Supplier Part Number 1=541-54.9KHCT-ND, TempCo="100 ppm/C", Tolerance_%=1%, Value2=0.1W, Value_Code=54k9, ValueDisplayed=54.9k
R23: library part CMP-0022066-4, "RES, 15.0 k, 1%, 0.1 W, AEC-Q200 Grade 0, 0603", Manufacturer=Vishay-Dale, Power_W=100mW, Supplier Part Number 1=541-15.0KHCT-ND, TempCo="100 ppm/C", Tolerance_%=1%, Value2=0.1W, Value_Code=15k0, ValueDisplayed=15.0k
R24: library part CMP-0020842-3, "RES, 10.0 k, 1%, 0.125 W, AEC-Q200 Grade 0, 0805", Manufacturer=Vishay-Dale, PartNumber=CRCW080510K0FKEA, Power_W=125mW, Supplier Part Number 1=541-10.0KCCT-ND, TempCo="100 ppm/C", Tolerance_%=1%, Value2=0.125W, Value_Code=10k0, ValueDisplayed=10.0k
R25: library part CMP-0022448-4, "RES, 49.9, 1%, 0.1 W, AEC-Q200 Grade 0, 0603", Manufacturer=Vishay-Dale, PartNumber=CRCW060349R9FKEA, Power_W=100mW, Supplier Part Number 1=541-49.9HCT-ND, TempCo="100 ppm/C", Tolerance_%=1%, Value2=0.1W, Value_Code=49R9, ValueDisplayed=49.9
R26 R28: library part CMP-0021998-4, "RES, 10.0 k, 1%, 0.1 W, AEC-Q200 Grade 0, 0603", Manufacturer=Vishay-Dale, Power_W=100mW, Supplier Part Number 1=541-10.0KHCT-ND, TempCo="100 ppm/C", Tolerance_%=1%, Value2=0.1W, Value_Code=10k0, ValueDisplayed=10.0k
R27: library part CMP-0022421-5, "RES, 432, 1%, 0.1 W, AEC-Q200 Grade 0, 0603", Manufacturer=Vishay-Dale, PartNumber=CRCW0603432RFKEA, Power_W=100mW, Supplier Part Number 1=541-432HCT-ND, TempCo="100 ppm/C", Tolerance_%=1%, Value2=0.1W, Value_Code=432R, ValueDisplayed=432
T1: library part CMP-0090899-1, "Flyback Converters For For AC/DC Converters SMPS Transformer 2600Vrms Isolation  Surface Mount", Digikey Part Number=445-180912-1-ND, Manufacturer=TDK, Mouser Part Number=810-VGT15SEFD250S4A7, Operating Temperature Range="-40°C to +130°C", Voltage_Isolation_Vrms=2.6kVrms
TP1 TP6 TP11: library part CMP-0055137-1, "Test Point, Miniature, Red, TH", Color=Red, Manufacturer=Keystone, Supplier Part Number 1=36-5000-ND
TP2 TP8 TP9 TP10: library part CMP-0055138-1, "Test Point, Miniature, Black, TH", Color=Black, Manufacturer=Keystone, Supplier Part Number 1=36-5001-ND
TP3: library part CMP-0067620-1, "PC Test Point, SMT", Manufacturer="TE Connectivity", Supplier Part Number 1=A106145CT-ND
TP4 TP7: library part CMP-0055140-1, "Test Point, Miniature, Orange, TH", Color=Orange, Manufacturer=Keystone, PartNumber=5003, Supplier Part Number 1=36-5003-ND
TP5: library part CMP-0055140-1, "Test Point, Miniature, Orange, TH", Color=Orange, Manufacturer=Keystone, Supplier Part Number 1=36-5003-ND
U1: library part CMP-0081540-1, "Automotive Grade 2.2-MHz Wide Input Non-synchronous Boost Controller, DSS0012C (WSON-12)", Alternate Manufacturer="Texas Instruments", Alternate PartNumber=LM51551QDSSRQ1

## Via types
v1: diameter 20, hole 10, Top Layer to Bottom Layer, 76 vias
v2: diameter 19.68, hole 7.87, Top Layer to Bottom Layer, 3 vias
